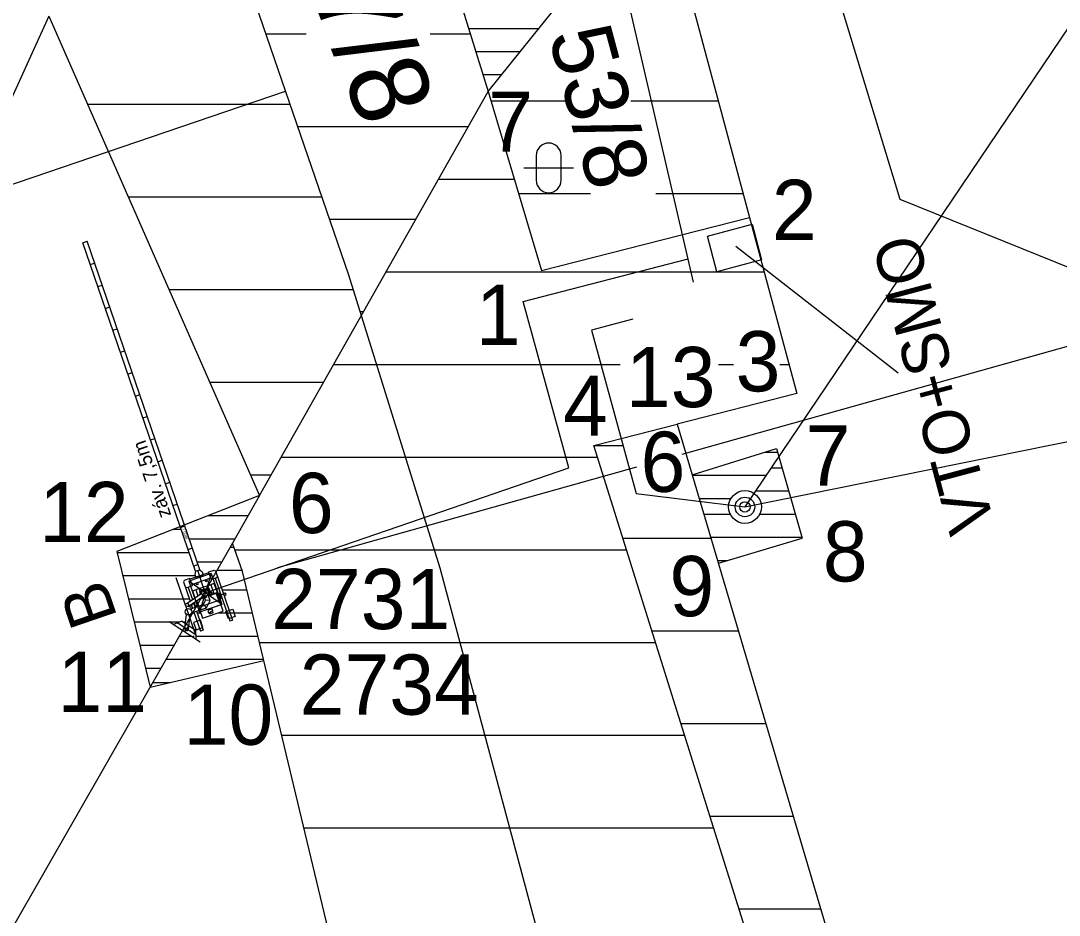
# Model space of a CAD drawing. Extents: x -553916 to -552953, y -1067469 to -1066637.
# Drawn here: x -553520.01 to -553497.58, y -1066999.11 to -1066979.8 of the extents above; entities that cross this region are included whole.
import ezdxf

# ---------------------------------------------------------------- set-up
doc = ezdxf.new("R2010")
doc.units = 0
for name, color, linetype in [('Hranice parcel', 7, 'Continuous'), ('Kolej', 7, 'Continuous'), ('Nová kabelizace', 7, 'Continuous'), ('nové prvky ZZ', 7, 'Continuous'), ('Propustek', 7, 'Continuous'), ('Přejezd - štěrkové lože', 7, 'Continuous'), ('trasa_NN_popisky', 7, 'Continuous'), ('trasa_NN_uzemneni', 7, 'Continuous'), ('Vrstva 1', 7, 'Continuous'), ('Vrstva 28', 7, 'Continuous'), ('Vrstva 58', 7, 'Continuous'), ('Vrstva 60', 7, 'Continuous'), ('Značky kultur', 7, 'Continuous')]:
    doc.layers.add(name, color=color, linetype=linetype)

msp = doc.modelspace()

# ---------------------------------------------------------------- linework, layer by layer
at = {"layer": 'Hranice parcel'}
msp.add_line((-553519.4, -1066979.7), (-553528.66, -1067000.03), dxfattribs=at)
for points in [[(-553481.25, -1066991.64), (-553501.02, -1066983.66), (-553503.13, -1066976.7), (-553485.37, -1066948.09)], [(-553515.43, -1066991.08), (-553526.38, -1067010.19), (-553539.65, -1067043.59), (-553548.33, -1067069.03)]]:
    msp.add_lwpolyline(points, dxfattribs=at)
at = {"layer": 'Kolej'}
msp.add_lwpolyline([(-553503.324, -1067065.808), (-553502.678, -1067054.027), (-553502.762, -1067041.504), (-553503.626, -1067029.057), (-553504.756, -1067019.974), (-553506.183, -1067011.388), (-553508.328, -1067001.388), (-553510.948, -1066991.622), (-553512.921, -1066985.291), (-553515.647, -1066977.347), (-553517.422, -1066972.53), (-553519.157, -1066967.95), (-553522.886, -1066958.375), (-553529.101, -1066942.549), (-553538.686, -1066918.107), (-553542.908, -1066907.329), (-553546.692, -1066897.676), (-553555.025, -1066876.441), (-553564.644, -1066851.894), (-553574.241, -1066827.427), (-553583.19, -1066804.618)], dxfattribs=at)
at = {"layer": 'Nová kabelizace'}
for p, q in [((-553505.478, -1066985.448), (-553507.017, -1066978.813)), ((-553509.157, -1066985.86), (-553505.596, -1066984.938)), ((-553508.173, -1066989.45), (-553509.157, -1066985.86)), ((-553516.02, -1066992.15), (-553508.173, -1066989.45))]:
    msp.add_line(p, q, dxfattribs=at)
at = {"layer": 'nové prvky ZZ'}
for p, q in [((-553505.18, -1066984.448), (-553504.213, -1066984.191)), ((-553504.213, -1066984.191), (-553504.008, -1066984.964)), ((-553518.666, -1066984.593), (-553518.572, -1066984.56)), ((-553516.232, -1066991.687), (-553518.666, -1066984.593)), ((-553516.138, -1066991.654), (-553518.572, -1066984.56)), ((-553504.568, -1066984.671), (-553501.059, -1066987.4)), ((-553518.504, -1066985.066), (-553518.41, -1066985.033)), ((-553518.341, -1066985.538), (-553518.248, -1066985.506)), ((-553518.179, -1066986.011), (-553518.085, -1066985.979)), ((-553518.017, -1066986.484), (-553517.923, -1066986.452)), ((-553517.855, -1066986.957), (-553517.761, -1066986.925)), ((-553517.692, -1066987.43), (-553517.598, -1066987.398)), ((-553517.53, -1066987.903), (-553517.436, -1066987.871)), ((-553517.368, -1066988.376), (-553517.274, -1066988.344)), ((-553517.205, -1066988.849), (-553517.112, -1066988.817)), ((-553517.043, -1066989.322), (-553516.949, -1066989.29)), ((-553516.881, -1066989.795), (-553516.787, -1066989.763)), ((-553516.719, -1066990.268), (-553516.625, -1066990.236)), ((-553516.556, -1066990.741), (-553516.462, -1066990.708)), ((-553516.394, -1066991.214), (-553516.3, -1066991.181)), ((-553516.176, -1066991.542), (-553516.27, -1066991.574)), ((-553515.895, -1066991.731), (-553516.377, -1066991.897)), ((-553516.232, -1066991.687), (-553516.138, -1066991.654)), ((-553516.222, -1066991.814), (-553516.065, -1066991.76)), ((-553516.02, -1066992.15), (-553516.185, -1066991.67)), ((-553515.895, -1066991.731), (-553516.145, -1066992.568)), ((-553515.946, -1066991.701), (-553515.827, -1066991.66)), ((-553515.941, -1066991.717), (-553515.946, -1066991.701)), ((-553515.895, -1066991.731), (-553515.664, -1066992.402)), ((-553515.827, -1066991.66), (-553515.798, -1066991.673)), ((-553515.798, -1066991.673), (-553515.432, -1066992.74)), ((-553516.241, -1066993.022), (-553516.65, -1066991.83)), ((-553516.476, -1066991.883), (-553516.491, -1066991.911)), ((-553516.491, -1066991.911), (-553516.348, -1066992.329)), ((-553516.357, -1066991.842), (-553516.476, -1066991.883)), ((-553516.302, -1066992.003), (-553516.421, -1066992.044)), ((-553516.377, -1066991.897), (-553516.145, -1066992.568)), ((-553515.664, -1066992.402), (-553516.377, -1066991.897)), ((-553516.352, -1066991.858), (-553516.357, -1066991.842)), ((-553516.313, -1066991.97), (-553516.302, -1066992.003)), ((-553515.899, -1066991.978), (-553516.224, -1066992.09)), ((-553515.902, -1066991.829), (-553515.891, -1066991.862)), ((-553515.894, -1066991.977), (-553515.899, -1066991.978)), ((-553515.899, -1066991.978), (-553515.833, -1066992.169)), ((-553515.826, -1066991.948), (-553515.895, -1066991.972)), ((-553515.895, -1066991.972), (-553515.894, -1066991.977)), ((-553515.891, -1066991.862), (-553515.772, -1066991.822)), ((-553515.748, -1066992.173), (-553515.826, -1066991.948)), ((-553515.806, -1066991.833), (-553515.488, -1066992.759)), ((-553515.772, -1066991.822), (-553515.757, -1066991.793)), ((-553516.421, -1066992.044), (-553516.45, -1066992.031)), ((-553516.433, -1066992.387), (-553516.092, -1066992.157)), ((-553516.393, -1066992.443), (-553516.052, -1066992.215)), ((-553516.387, -1066992.033), (-553516.297, -1066992.295)), ((-553516.3, -1066992.111), (-553516.23, -1066992.087)), ((-553516.3, -1066992.111), (-553516.248, -1066992.262)), ((-553516.23, -1066992.087), (-553516.228, -1066992.091)), ((-553516.228, -1066992.091), (-553516.224, -1066992.09)), ((-553516.224, -1066992.09), (-553516.18, -1066992.216)), ((-553516.106, -1066992.104), (-553516.125, -1066992.116)), ((-553516.125, -1066992.116), (-553516.111, -1066992.136)), ((-553516.106, -1066992.166), (-553516.113, -1066992.146)), ((-553516.111, -1066992.136), (-553516.093, -1066992.124)), ((-553516.096, -1066992.159), (-553516.102, -1066992.142)), ((-553516.06, -1066992.081), (-553516.095, -1066992.103)), ((-553516.077, -1066992.105), (-553516.089, -1066992.113)), ((-553516.038, -1066992.237), (-553516.045, -1066992.218)), ((-553516.04, -1066992.238), (-553516.024, -1066992.227)), ((-553516.025, -1066992.152), (-553516.015, -1066992.148)), ((-553516.022, -1066992.145), (-553516.019, -1066992.155)), ((-553516.001, -1066992.22), (-553516.012, -1066992.228)), ((-553515.97, -1066992.211), (-553516.006, -1066992.237)), ((-553515.917, -1066992.32), (-553515.958, -1066992.2)), ((-553515.792, -1066992.155), (-553515.954, -1066992.211)), ((-553515.928, -1066992.156), (-553515.951, -1066992.09)), ((-553515.789, -1066992.166), (-553515.951, -1066992.221)), ((-553515.918, -1066992.148), (-553515.939, -1066992.087)), ((-553515.897, -1066992.14), (-553515.93, -1066992.151)), ((-553515.894, -1066992.151), (-553515.92, -1066992.16)), ((-553515.888, -1066992.141), (-553515.897, -1066992.14)), ((-553515.885, -1066992.151), (-553515.894, -1066992.151)), ((-553515.878, -1066992.146), (-553515.888, -1066992.141)), ((-553515.874, -1066992.183), (-553515.885, -1066992.151)), ((-553515.872, -1066992.153), (-553515.878, -1066992.146)), ((-553515.863, -1066992.179), (-553515.872, -1066992.153)), ((-553515.774, -1066992.155), (-553515.792, -1066992.155)), ((-553515.777, -1066992.17), (-553515.789, -1066992.166)), ((-553515.726, -1066992.317), (-553515.777, -1066992.17)), ((-553515.763, -1066992.169), (-553515.774, -1066992.155)), ((-553515.713, -1066992.312), (-553515.763, -1066992.169)), ((-553515.69, -1066992.251), (-553515.712, -1066992.189)), ((-553515.682, -1066992.193), (-553515.645, -1066992.18)), ((-553515.645, -1066992.18), (-553515.636, -1066992.18)), ((-553515.636, -1066992.18), (-553515.622, -1066992.185)), ((-553515.586, -1066992.162), (-553515.597, -1066992.166)), ((-553515.584, -1066992.167), (-553515.586, -1066992.162)), ((-553515.574, -1066992.195), (-553515.586, -1066992.199)), ((-553515.577, -1066992.164), (-553515.584, -1066992.167)), ((-553515.569, -1066992.188), (-553515.577, -1066992.164)), ((-553515.569, -1066992.188), (-553515.576, -1066992.191)), ((-553515.576, -1066992.191), (-553515.574, -1066992.195)), ((-553516.364, -1066992.434), (-553516.357, -1066992.432)), ((-553516.356, -1066992.458), (-553516.364, -1066992.434)), ((-553516.359, -1066992.428), (-553516.347, -1066992.424)), ((-553516.357, -1066992.432), (-553516.359, -1066992.428)), ((-553516.056, -1066992.404), (-553516.342, -1066992.502)), ((-553516.324, -1066992.397), (-553516.294, -1066992.486)), ((-553516.308, -1066992.41), (-553516.315, -1066992.423)), ((-553516.301, -1066992.405), (-553516.308, -1066992.41)), ((-553516.264, -1066992.392), (-553516.301, -1066992.405)), ((-553516.274, -1066992.363), (-553516.238, -1066992.467)), ((-553516.212, -1066992.323), (-553516.218, -1066992.334)), ((-553516.183, -1066992.409), (-553516.212, -1066992.322)), ((-553516.16, -1066992.44), (-553516.203, -1066992.316)), ((-553516.034, -1066992.25), (-553516.178, -1066992.299)), ((-553515.663, -1066992.402), (-553516.145, -1066992.568)), ((-553515.72, -1066992.422), (-553516.145, -1066992.568)), ((-553516.039, -1066992.24), (-553516.142, -1066992.275)), ((-553516.056, -1066992.404), (-553516.013, -1066992.312)), ((-553515.995, -1066992.476), (-553516.056, -1066992.404)), ((-553516.027, -1066992.259), (-553516.04, -1066992.238)), ((-553516.013, -1066992.312), (-553516.035, -1066992.245)), ((-553516.01, -1066992.247), (-553516.027, -1066992.259)), ((-553515.917, -1066992.32), (-553516.013, -1066992.312)), ((-553515.995, -1066992.476), (-553515.917, -1066992.32)), ((-553516.464, -1066992.923), (-553516.429, -1066992.616)), ((-553516.385, -1066992.933), (-553516.349, -1066992.625)), ((-553516.356, -1066992.458), (-553516.349, -1066992.456)), ((-553516.349, -1066992.456), (-553516.347, -1066992.46)), ((-553516.347, -1066992.46), (-553516.336, -1066992.456)), ((-553516.316, -1066992.586), (-553515.995, -1066992.476)), ((-553516.265, -1066992.569), (-553516.125, -1066992.978)), ((-553516.21, -1066992.549), (-553516.069, -1066992.958)), ((-553515.86, -1066992.547), (-553515.857, -1066992.546)), ((-553516.132, -1066993.216), (-553516.803, -1066992.78)), ((-553516.719, -1066992.834), (-553516.533, -1066992.76)), ((-553516.22, -1066993.062), (-553516.626, -1066992.797)), ((-553516.223, -1066992.962), (-553516.533, -1066992.76)), ((-553516.467, -1066992.998), (-553516.378, -1066992.861)), ((-553515.488, -1066992.759), (-553515.432, -1066992.74)), ((-553516.414, -1066992.928), (-553516.431, -1066992.931)), ((-553516.424, -1066992.921), (-553516.422, -1066992.938)), ((-553516.216, -1066993.162), (-553516.223, -1066992.962)), ((-553516.069, -1066992.958), (-553516.125, -1066992.978))]:
    msp.add_line(p, q, dxfattribs=at)
for points in [[(-553504.008, -1066984.964), (-553504.974, -1066985.221), (-553505.18, -1066984.448)], [(-553516.232, -1066991.687), (-553516.244, -1066991.755), (-553516.223, -1066991.814)], [(-553516.138, -1066991.654), (-553516.086, -1066991.701), (-553516.066, -1066991.76)], [(-553516.202, -1066991.973), (-553516.207, -1066991.974), (-553516.22, -1066991.938), (-553516.192, -1066991.929), (-553516.179, -1066991.965), (-553516.184, -1066991.966)], [(-553516.184, -1066991.966), (-553516.182, -1066991.974), (-553516.2, -1066991.981), (-553516.202, -1066991.973)], [(-553516.004, -1066991.904), (-553516.008, -1066991.906), (-553516.021, -1066991.87), (-553515.993, -1066991.861), (-553515.981, -1066991.897), (-553515.986, -1066991.898)], [(-553515.986, -1066991.898), (-553515.983, -1066991.906), (-553516.001, -1066991.912), (-553516.004, -1066991.904)], [(-553516.109, -1066992.095), (-553516.113, -1066992.085), (-553516.151, -1066992.099), (-553516.135, -1066992.144)], [(-553516.112, -1066992.135), (-553516.145, -1066992.147), (-553516.141, -1066992.156), (-553516.092, -1066992.139)], [(-553516.085, -1066992.118), (-553516.103, -1066992.091), (-553516.111, -1066992.096), (-553516.089, -1066992.128)], [(-553516.09, -1066992.128), (-553516.107, -1066992.134)], [(-553516.016, -1066992.222), (-553515.998, -1066992.25), (-553516.005, -1066992.255), (-553516.027, -1066992.222)], [(-553515.971, -1066992.087), (-553515.934, -1066992.075), (-553515.95, -1066992.03), (-553515.988, -1066992.043), (-553515.974, -1066992.086)], [(-553515.963, -1066992.095), (-553515.923, -1066992.081), (-553515.926, -1066992.072), (-553515.971, -1066992.087), (-553515.971, -1066992.088)], [(-553515.943, -1066992.168), (-553515.942, -1066992.171), (-553515.916, -1066992.162), (-553515.919, -1066992.153), (-553515.942, -1066992.161)], [(-553515.712, -1066992.189), (-553515.72, -1066992.164), (-553515.753, -1066992.175), (-553515.726, -1066992.252)], [(-553515.69, -1066992.251), (-553515.678, -1066992.247), (-553515.7, -1066992.185), (-553515.712, -1066992.189)], [(-553515.617, -1066992.169), (-553515.621, -1066992.157), (-553515.631, -1066992.161), (-553515.609, -1066992.224), (-553515.6, -1066992.221), (-553515.603, -1066992.209)], [(-553515.597, -1066992.166), (-553515.599, -1066992.162), (-553515.617, -1066992.169)], [(-553515.603, -1066992.209), (-553515.585, -1066992.203), (-553515.586, -1066992.199)], [(-553516.347, -1066992.424), (-553516.348, -1066992.419), (-553516.33, -1066992.413)], [(-553516.33, -1066992.413), (-553516.333, -1066992.403)], [(-553516.329, -1066992.4), (-553516.324, -1066992.399), (-553516.302, -1066992.462), (-553516.312, -1066992.465), (-553516.316, -1066992.454)], [(-553516.264, -1066992.357), (-553516.229, -1066992.458), (-553516.24, -1066992.462), (-553516.274, -1066992.363)], [(-553516.218, -1066992.432), (-553516.236, -1066992.438), (-553516.257, -1066992.376), (-553516.24, -1066992.37)], [(-553516.24, -1066992.37), (-553516.248, -1066992.346)], [(-553516.244, -1066992.343), (-553516.217, -1066992.334), (-553516.191, -1066992.412)], [(-553516.21, -1066992.457), (-553516.218, -1066992.432)], [(-553516.187, -1066992.449), (-553516.199, -1066992.414), (-553516.183, -1066992.409), (-553516.171, -1066992.444)], [(-553515.704, -1066992.285), (-553515.682, -1066992.277), (-553515.69, -1066992.251)], [(-553516.316, -1066992.454), (-553516.334, -1066992.46), (-553516.336, -1066992.456)], [(-553515.857, -1066992.546), (-553515.874, -1066992.498), (-553515.968, -1066992.53), (-553515.949, -1066992.584), (-553515.909, -1066992.57)], [(-553515.905, -1066992.583), (-553515.932, -1066992.592), (-553515.928, -1066992.604), (-553515.901, -1066992.594)], [(-553515.901, -1066992.594), (-553515.849, -1066992.577), (-553515.86, -1066992.547), (-553515.911, -1066992.564), (-553515.905, -1066992.583)]]:
    msp.add_lwpolyline(points, dxfattribs=at)
for points in [[(-553515.902, -1066991.829), (-553515.941, -1066991.717), (-553516.352, -1066991.858), (-553516.313, -1066991.97)], [(-553516.121, -1066992.088), (-553516.126, -1066992.073), (-553516.148, -1066992.081), (-553516.143, -1066992.096)], [(-553515.958, -1066992.033), (-553515.963, -1066992.017), (-553515.985, -1066992.025), (-553515.98, -1066992.04)], [(-553515.922, -1066992.164), (-553515.919, -1066992.171), (-553515.936, -1066992.177), (-553515.939, -1066992.17)], [(-553515.658, -1066992.262), (-553515.694, -1066992.16), (-553515.707, -1066992.164), (-553515.672, -1066992.267)], [(-553515.634, -1066992.544), (-553515.713, -1066992.312), (-553516.163, -1066992.467), (-553516.083, -1066992.699)], [(-553515.7, -1066992.298), (-553515.717, -1066992.249), (-553515.733, -1066992.254), (-553515.716, -1066992.303)], [(-553515.521, -1066992.71), (-553515.574, -1066992.555), (-553515.428, -1066992.504), (-553515.375, -1066992.66)], [(-553516.073, -1066992.899), (-553516.126, -1066992.744), (-553516.273, -1066992.794), (-553516.219, -1066992.95)]]:
    msp.add_lwpolyline(points, close=True, dxfattribs=at)
for centre, radius in [((-553516.02, -1066992.15), 0.0725), ((-553516.413, -1066992.415), 0.0347), ((-553516.383, -1066992.561), 0.0716), ((-553516.423, -1066992.929), 0.00856)]:
    msp.add_circle(centre, radius, dxfattribs=at)
for centre, radius, start, end in [((-553516.02, -1066992.15), 0.0795, 309.387, 119.921), ((-553516.424, -1066992.927), 0.0399, 173.2567, 354.9637)]:
    msp.add_arc(centre, radius, start, end, dxfattribs=at)
at = {"layer": 'Propustek'}
for p, q in [((-553514.85, -1066990.05), (-553509.91, -1066981.33)), ((-553510.982, -1066983.222), (-553509.346, -1066983.222)), ((-553504.27, -1066984.05), (-553503.25, -1066987.85)), ((-553512.115, -1066985.222), (-553503.955, -1066985.222)), ((-553513.248, -1066987.222), (-553507.063, -1066987.222)), ((-553504.941, -1066987.222), (-553504.613, -1066987.222)), ((-553503.618, -1066987.222), (-553503.419, -1066987.222)), ((-553503.25, -1066987.85), (-553505.83, -1066988.51)), ((-553505.83, -1066988.51), (-553499.28, -1067010.65)), ((-553507.63, -1066988.97), (-553507, -1066988.97)), ((-553514.381, -1066989.222), (-553507.551, -1066989.222)), ((-553507.003, -1066990.97), (-553505.102, -1066990.97)), ((-553515.381, -1066991.222), (-553506.924, -1066991.222)), ((-553506.376, -1066992.97), (-553504.511, -1066992.97)), ((-553514.853, -1066993.222), (-553506.297, -1066993.222)), ((-553505.749, -1066994.97), (-553503.919, -1066994.97)), ((-553514.374, -1066995.222), (-553505.67, -1066995.222)), ((-553505.121, -1066996.97), (-553503.327, -1066996.97)), ((-553513.895, -1066997.222), (-553505.042, -1066997.222)), ((-553504.494, -1066998.97), (-553502.735, -1066998.97))]:
    msp.add_line(p, q, dxfattribs=at)
for points in [[(-553509.91, -1066981.33), (-553508.76, -1066985.19), (-553504.27, -1066984.05)], [(-553498.68, -1067074.42), (-553498.17, -1067040.43), (-553500.08, -1067020.73), (-553503.77, -1067001.28), (-553507.63, -1066988.97), (-553505.83, -1066988.51)], [(-553509.03, -1067072.35), (-553507.22, -1067040.68), (-553509.18, -1067016.9), (-553515.22, -1066991.69), (-553515.43, -1066991.08)]]:
    msp.add_lwpolyline(points, dxfattribs=at)
at = {"layer": 'Přejezd - štěrkové lože'}
msp.add_lwpolyline([(-553573.367, -1066993.961), (-553535.151, -1066981.6), (-553526.82, -1066985.587), (-553514.291, -1066981.32)], dxfattribs=at)
at = {"layer": 'trasa_NN_popisky'}
msp.add_lwpolyline([(-553456.479, -1066963.507), (-553494.623, -1066975.849), (-553504.368, -1066990.297)], dxfattribs=at)
at = {"layer": 'trasa_NN_uzemneni'}
msp.add_lwpolyline([(-553506.79, -1066986.24), (-553507.681, -1066986.481), (-553506.717, -1066990.005), (-553504.368, -1066990.297)], dxfattribs=at)
for radius in [0.354, 0.211, 0.111]:
    msp.add_circle((-553504.368, -1066990.297), radius, dxfattribs=at)
at = {"layer": 'Vrstva 1'}
for p, q in [((-553509.91, -1066981.33), (-553506.23, -1066976.75)), ((-553506.23, -1066976.75), (-553504.27, -1066984.05)), ((-553519.4, -1066979.7), (-553514.85, -1066990.05)), ((-553510.334, -1066979.965), (-553508.813, -1066979.965)), ((-553510.178, -1066980.465), (-553509.215, -1066980.465)), ((-553510.023, -1066980.965), (-553509.617, -1066980.965)), ((-553505.506, -1066989.604), (-553503.69, -1066989.038)), ((-553503.69, -1066989.038), (-553503.132, -1066990.969)), ((-553503.93, -1066989.113), (-553503.669, -1066989.113)), ((-553503.798, -1066989.452), (-553503.571, -1066989.452)), ((-553505.504, -1066989.613), (-553503.906, -1066989.613)), ((-553504.135, -1066989.952), (-553503.426, -1066989.952)), ((-553514.85, -1066990.05), (-553517.928, -1066991.256)), ((-553514.85, -1066990.05), (-553516.997, -1066990.892)), ((-553514.85, -1066990.05), (-553515.43, -1066991.08)), ((-553505.356, -1066990.113), (-553504.67, -1066990.113)), ((-553515.951, -1066990.482), (-553515.093, -1066990.482)), ((-553505.255, -1066990.452), (-553504.685, -1066990.452)), ((-553504.05, -1066990.452), (-553503.282, -1066990.452)), ((-553516.706, -1066990.778), (-553516.543, -1066990.778)), ((-553516.997, -1066990.892), (-553517.928, -1066991.256)), ((-553516.368, -1066990.982), (-553515.375, -1066990.982)), ((-553505.108, -1066990.952), (-553503.137, -1066990.952)), ((-553504.941, -1066991.514), (-553503.132, -1066990.969)), ((-553517.928, -1066991.256), (-553517.209, -1066994.185)), ((-553517.923, -1066991.278), (-553516.372, -1066991.278)), ((-553515.477, -1066991.162), (-553515.402, -1066991.162)), ((-553516.197, -1066991.482), (-553515.66, -1066991.482)), ((-553504.96, -1066991.452), (-553504.735, -1066991.452)), ((-553517.8, -1066991.778), (-553516.236, -1066991.778)), ((-553515.763, -1066991.662), (-553515.23, -1066991.662)), ((-553515.657, -1066992.084), (-553515.126, -1066992.084)), ((-553517.677, -1066992.278), (-553516.365, -1066992.278)), ((-553516.292, -1066992.584), (-553516.26, -1066992.584)), ((-553516.198, -1066992.584), (-553516.123, -1066992.584)), ((-553515.749, -1066992.584), (-553515.564, -1066992.584)), ((-553515.657, -1066992.584), (-553515.126, -1066992.584)), ((-553515.401, -1066992.584), (-553515.006, -1066992.584)), ((-553517.554, -1066992.778), (-553516.578, -1066992.778)), ((-553516.506, -1066992.778), (-553516.447, -1066992.778)), ((-553516.578, -1066993.084), (-553516.335, -1066993.084)), ((-553516.292, -1066993.084), (-553516.26, -1066993.084)), ((-553516.219, -1066993.084), (-553514.886, -1066993.084)), ((-553516.198, -1066993.084), (-553516.123, -1066993.084)), ((-553515.749, -1066993.084), (-553515.564, -1066993.084)), ((-553515.401, -1066993.084), (-553515.006, -1066993.084)), ((-553517.432, -1066993.278), (-553516.689, -1066993.278)), ((-553517.309, -1066993.778), (-553516.976, -1066993.778)), ((-553517.209, -1066994.185), (-553514.76, -1066993.609)), ((-553516.865, -1066993.584), (-553515.804, -1066993.584)), ((-553516.578, -1066993.584), (-553516.335, -1066993.584)), ((-553516.219, -1066993.584), (-553514.766, -1066993.584)), ((-553517.151, -1066994.084), (-553516.781, -1066994.084))]:
    msp.add_line(p, q, dxfattribs=at)
msp.add_lwpolyline([(-553513.35, -1066970.96), (-553513.02, -1066971.31), (-553509.91, -1066981.33)], dxfattribs=at)
at = {"layer": 'Vrstva 28'}
for p, q in [((-553261.015, -1066920.514), (-553505.733, -1066989.165)), ((-553504.368, -1066990.297), (-553260.214, -1066940.912)), ((-553506.707, -1066989.438), (-553514.461, -1066991.614))]:
    msp.add_line(p, q, dxfattribs=at)
at = {"layer": 'Vrstva 58'}
for p, q in [((-553514.709, -1066980.081), (-553513.84, -1066980.081)), ((-553511.167, -1066980.081), (-553510.298, -1066980.081)), ((-553518.563, -1066981.603), (-553514.187, -1066981.603)), ((-553509.851, -1066981.528), (-553508.238, -1066981.528)), ((-553506.83, -1066981.528), (-553504.947, -1066981.528)), ((-553514.023, -1066982.081), (-553510.335, -1066982.081)), ((-553517.684, -1066983.603), (-553513.5, -1066983.603)), ((-553509.255, -1066983.528), (-553507.702, -1066983.528)), ((-553506.294, -1066983.528), (-553504.41, -1066983.528)), ((-553513.336, -1066984.081), (-553511.468, -1066984.081)), ((-553516.805, -1066985.603), (-553512.824, -1066985.603)), ((-553512.675, -1066986.081), (-553512.602, -1066986.081)), ((-553515.926, -1066987.603), (-553513.464, -1066987.603)), ((-553515.047, -1066989.603), (-553514.597, -1066989.603))]:
    msp.add_line(p, q, dxfattribs=at)
at = {"layer": 'Vrstva 60'}
for p, q in [((-553509.91, -1066981.33), (-553509.91, -1066981.33)), ((-553504.27, -1066984.05), (-553504.27, -1066984.05)), ((-553508.76, -1066985.19), (-553508.76, -1066985.19)), ((-553503.25, -1066987.85), (-553503.25, -1066987.85)), ((-553505.83, -1066988.51), (-553505.83, -1066988.51)), ((-553507.63, -1066988.97), (-553507.63, -1066988.97)), ((-553503.691, -1066989.039), (-553503.691, -1066989.039)), ((-553505.506, -1066989.604), (-553505.506, -1066989.604)), ((-553514.85, -1066990.05), (-553514.85, -1066990.05)), ((-553515.43, -1066991.08), (-553515.43, -1066991.08)), ((-553503.132, -1066990.969), (-553503.132, -1066990.969)), ((-553517.929, -1066991.256), (-553517.929, -1066991.256)), ((-553504.941, -1066991.514), (-553504.941, -1066991.514)), ((-553515.22, -1066991.69), (-553515.22, -1066991.69)), ((-553514.76, -1066993.609), (-553514.76, -1066993.609)), ((-553517.209, -1066994.185), (-553517.209, -1066994.185))]:
    msp.add_line(p, q, dxfattribs=at)
at = {"layer": 'Značky kultur'}
for p, q in [((-553508.874, -1066982.708), (-553508.874, -1066983.245)), ((-553508.338, -1066983.245), (-553508.338, -1066982.708)), ((-553509.143, -1066982.977), (-553508.069, -1066982.977))]:
    msp.add_line(p, q, dxfattribs=at)
for centre, start, end in [((-553508.606, -1066982.709), 0, 180), ((-553508.606, -1066983.245), 180, 359.9879)]:
    msp.add_arc(centre, 0.268, start, end, dxfattribs=at)

# ---------------------------------------------------------------- texts
at = {"layer": 'nové prvky ZZ'}
for s, height, rotation, p in [('VTO+SMO', 1, 104.9376, (-553498.965, -1066990.707)), ('záv. 7,5m', 0.3, 109.138, (-553516.752, -1066990.475)), ('7,50m', 0.0646, 288.9398, (-553516.526, -1066990.764)), ('B', 1.025, 108.8917, (-553517.911, -1066992.68)), ('265', 0.025, 288.9398, (-553515.996, -1066992.119))]:
    msp.add_text(s, height=height, rotation=rotation, dxfattribs=at).set_placement(p)
at = {"layer": 'Vrstva 1'}
for s, height, rotation, p in [('1517/8', 1.7, 290.9878, (-553515.1, -1066975.676)), ('53/8', 1.36, 285, (-553508.618, -1066980.11))]:
    msp.add_text(s, height=height, rotation=rotation, dxfattribs=at).set_placement(p)
at = {"layer": 'Vrstva 60'}
for s, p in [('7', (-553509.91, -1066982.63)), ('2', (-553503.788, -1066984.535)), ('1', (-553510.177, -1066986.8)), ('3', (-553504.569, -1066987.802)), ('13', (-553506.938, -1066988.143)), ('4', (-553508.296, -1066988.761)), ('7', (-553503.058, -1066989.837)), ('6', (-553506.622, -1066989.972)), ('12', (-553519.609, -1066991.057)), ('6', (-553514.215, -1066990.861)), ('8', (-553502.686, -1066991.906)), ('9', (-553505.999, -1066992.656)), ('2731', (-553514.599, -1066992.934)), ('11', (-553519.211, -1066994.721)), ('2734', (-553513.982, -1066994.782)), ('10', (-553516.487, -1066995.431))]:
    msp.add_text(s, height=1.3, dxfattribs=at).set_placement(p)

doc.saveas('drawing.dxf')
